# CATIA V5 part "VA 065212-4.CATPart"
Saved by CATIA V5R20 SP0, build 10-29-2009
Part number: VA 065212-4
Revision: ANY
Definition: UNKNOWN
Nomenclature: VA 065212-4
Source: Unknown
Bounding box of the stored display mesh (mm): x -2.312 to 2.312, y 0 to 2.9, z -1.75 to 1.75
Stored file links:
  C:\Users\Utente\Desktop\IO LAVORO\3D X SITO CF\CUMSA\3D files VA\VA 065212\VA 065212-4.CATPart
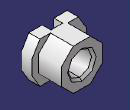
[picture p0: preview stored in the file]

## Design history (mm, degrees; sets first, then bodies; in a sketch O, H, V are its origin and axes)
Body1 "Chaflán1" (main body)
  Solid1: solid without history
